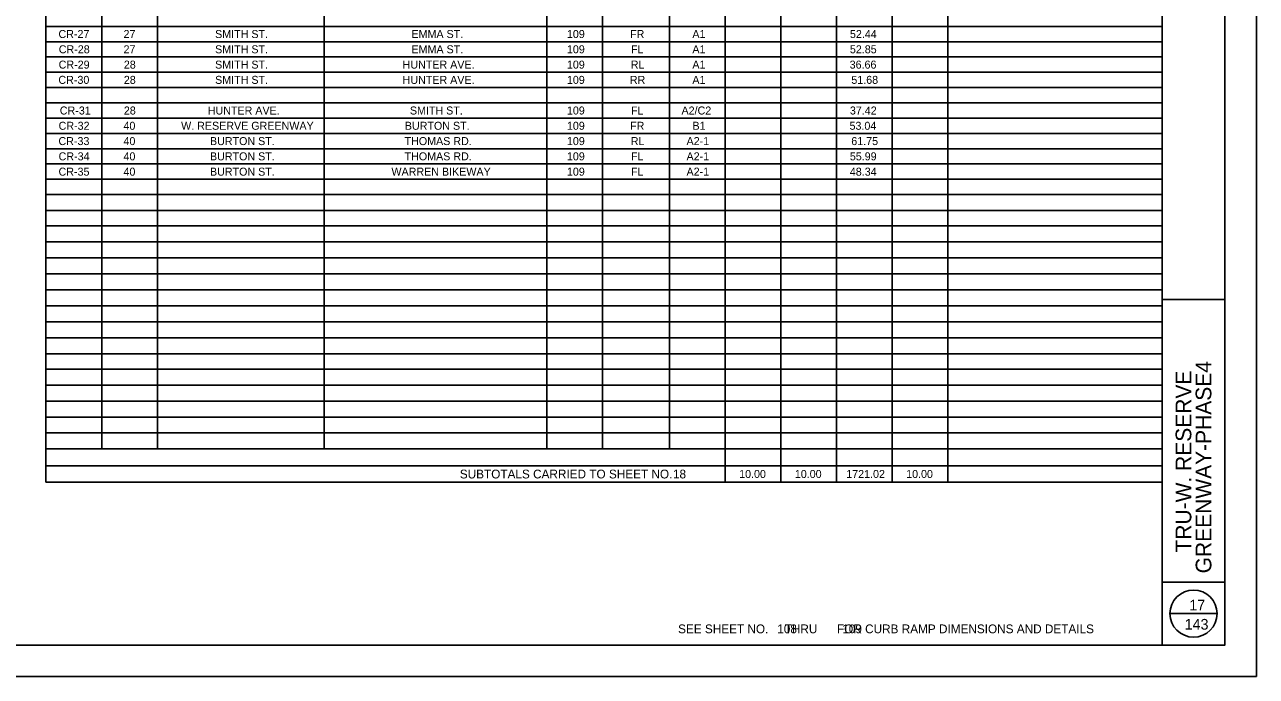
# Model space of a CAD drawing. Extents: x -16 to 102, y -13 to 9.
# Drawn here: x -1.97 to 17.63, y -12.91 to -2.53 of the extents above; entities that cross this region are included whole.
import ezdxf

# ---------------------------------------------------------------- set-up
doc = ezdxf.new("R2010")
doc.units = 0
for name, color, linetype in [('PV_P_EOP', 7, 'Continuous'), ('SH_Border', 7, 'Continuous'), ('SH_Cut_Line', 7, 'Continuous'), ('SH_Data', 7, 'Continuous'), ('TX_P_1', 7, 'Continuous')]:
    doc.layers.add(name, color=color, linetype=linetype)

msp = doc.modelspace()

# ---------------------------------------------------------------- linework, layer by layer
at = {"layer": 'SH_Border'}
for p, q in [((16.129, -12.407), (16.129, 8.593)), ((16.129, -6.907), (17.129, -6.907)), ((16.129, -11.407), (17.129, -11.407))]:
    msp.add_line(p, q, dxfattribs=at)
msp.add_lwpolyline([(-14.371, 8.593), (17.129, 8.593), (17.129, -12.407), (-14.371, -12.407)], close=True, dxfattribs=at)
at = {"layer": 'SH_Cut_Line'}
msp.add_lwpolyline([(-16.371, -12.907), (17.629, -12.907), (17.629, 9.093), (-16.371, 9.093)], close=True, dxfattribs=at)
at = {"layer": 'SH_Data'}
msp.add_line((16.254, -11.907), (17.004, -11.907), dxfattribs=at)
msp.add_circle((16.629, -11.907), 0.375, dxfattribs=at)
at = {"layer": 'TX_P_1'}
for p, q in [((-1.628, -2.067), (-1.628, -2.798)), ((-0.742, -2.067), (-0.742, -2.798)), ((0.144, -2.067), (0.144, -2.798)), ((2.8, -2.067), (2.8, -2.798)), ((6.343, -2.067), (6.343, -2.798)), ((7.228, -2.067), (7.228, -2.798)), ((8.291, -2.067), (8.291, -2.798)), ((9.177, -2.067), (9.177, -2.798)), ((10.062, -2.067), (10.062, -2.798)), ((10.948, -2.067), (10.948, -2.798)), ((11.834, -2.067), (11.834, -2.798)), ((12.719, -2.067), (12.719, -2.798)), ((16.129, -2.067), (16.129, -2.798)), ((-1.628, -2.554), (16.129, -2.554)), ((-1.628, -2.798), (16.129, -2.798)), ((-1.628, -2.798), (-1.628, -3.285)), ((-0.742, -2.798), (-0.742, -3.285)), ((0.144, -2.798), (0.144, -3.285)), ((2.8, -2.798), (2.8, -3.285)), ((6.343, -2.798), (6.343, -3.285)), ((7.228, -2.798), (7.228, -3.285)), ((8.291, -2.798), (8.291, -3.285)), ((9.177, -2.798), (9.177, -3.285)), ((10.062, -2.798), (10.062, -3.285)), ((10.948, -2.798), (10.948, -3.285)), ((11.834, -2.798), (11.834, -3.285)), ((12.719, -2.798), (12.719, -3.285)), ((16.129, -2.798), (16.129, -3.285)), ((-1.628, -3.042), (16.129, -3.042)), ((-1.628, -3.285), (16.129, -3.285)), ((-1.628, -3.285), (-1.628, -4.016)), ((-0.742, -3.285), (-0.742, -4.016)), ((0.144, -3.285), (0.144, -4.016)), ((2.8, -3.285), (2.8, -4.016)), ((6.343, -3.285), (6.343, -4.016)), ((7.228, -3.285), (7.228, -4.016)), ((8.291, -3.285), (8.291, -4.016)), ((9.177, -3.285), (9.177, -4.016)), ((10.062, -3.285), (10.062, -4.016)), ((10.948, -3.285), (10.948, -4.016)), ((11.834, -3.285), (11.834, -4.016)), ((12.719, -3.285), (12.719, -4.016)), ((16.129, -3.285), (16.129, -4.016)), ((-1.628, -3.529), (16.129, -3.529)), ((-1.628, -3.772), (16.129, -3.772)), ((-1.628, -4.016), (16.129, -4.016)), ((-1.628, -4.016), (-1.628, -4.503)), ((-0.742, -4.016), (-0.742, -4.503)), ((0.144, -4.016), (0.144, -4.503)), ((2.8, -4.016), (2.8, -4.503)), ((6.343, -4.016), (6.343, -4.503)), ((7.228, -4.016), (7.228, -4.503)), ((8.291, -4.016), (8.291, -4.503)), ((9.177, -4.016), (9.177, -4.503)), ((10.062, -4.016), (10.062, -4.503)), ((10.948, -4.016), (10.948, -4.503)), ((11.834, -4.016), (11.834, -4.503)), ((12.719, -4.016), (12.719, -4.503)), ((16.129, -4.016), (16.129, -4.503)), ((-1.628, -4.259), (16.129, -4.259)), ((-1.628, -4.503), (16.129, -4.503)), ((-1.628, -4.503), (-1.628, -5.233)), ((-0.742, -4.503), (-0.742, -5.233)), ((0.144, -4.503), (0.144, -5.233)), ((2.8, -4.503), (2.8, -5.233)), ((6.343, -4.503), (6.343, -5.233)), ((7.228, -4.503), (7.228, -5.233)), ((8.291, -4.503), (8.291, -5.233)), ((9.177, -4.503), (9.177, -5.233)), ((10.062, -4.503), (10.062, -5.233)), ((10.948, -4.503), (10.948, -5.233)), ((11.834, -4.503), (11.834, -5.233)), ((12.719, -4.503), (12.719, -5.233)), ((16.129, -4.503), (16.129, -5.233)), ((-1.628, -4.746), (16.129, -4.746)), ((-1.628, -4.99), (16.129, -4.99)), ((-1.628, -5.233), (16.129, -5.233)), ((-1.628, -5.233), (-1.628, -5.488)), ((-0.742, -5.233), (-0.742, -5.488)), ((0.144, -5.233), (0.144, -5.488)), ((2.8, -5.233), (2.8, -5.488)), ((6.343, -5.233), (6.343, -5.488)), ((7.228, -5.233), (7.228, -5.488)), ((8.291, -5.233), (8.291, -5.488)), ((9.177, -5.233), (9.177, -5.488)), ((10.062, -5.233), (10.062, -5.488)), ((10.948, -5.233), (10.948, -5.488)), ((11.834, -5.233), (11.834, -5.488)), ((12.719, -5.233), (12.719, -5.488)), ((16.129, -5.233), (16.129, -5.488)), ((-1.628, -5.488), (16.129, -5.488)), ((-1.628, -5.488), (-1.628, -5.732)), ((-0.742, -5.488), (-0.742, -5.732)), ((0.144, -5.488), (0.144, -5.732)), ((2.8, -5.488), (2.8, -5.732)), ((6.343, -5.488), (6.343, -5.732)), ((7.228, -5.488), (7.228, -5.732)), ((8.291, -5.488), (8.291, -5.732)), ((9.177, -5.488), (9.177, -5.732)), ((10.062, -5.488), (10.062, -5.732)), ((10.948, -5.488), (10.948, -5.732)), ((11.834, -5.488), (11.834, -5.732)), ((12.719, -5.488), (12.719, -5.732)), ((16.129, -5.488), (16.129, -5.732)), ((-1.628, -5.732), (16.129, -5.732)), ((-1.628, -5.732), (-1.628, -5.986)), ((-0.742, -5.732), (-0.742, -5.986)), ((0.144, -5.732), (0.144, -5.986)), ((2.8, -5.732), (2.8, -5.986)), ((6.343, -5.732), (6.343, -5.986)), ((7.228, -5.732), (7.228, -5.986)), ((8.291, -5.732), (8.291, -5.986)), ((9.177, -5.732), (9.177, -5.986)), ((10.062, -5.732), (10.062, -5.986)), ((10.948, -5.732), (10.948, -5.986)), ((11.834, -5.732), (11.834, -5.986)), ((12.719, -5.732), (12.719, -5.986)), ((16.129, -5.732), (16.129, -5.986)), ((-1.628, -5.986), (16.129, -5.986)), ((-1.628, -5.986), (-1.628, -6.75)), ((-0.742, -5.986), (-0.742, -6.75)), ((0.144, -5.986), (0.144, -6.75)), ((2.8, -5.986), (2.8, -6.75)), ((6.343, -5.986), (6.343, -6.75)), ((7.228, -5.986), (7.228, -6.75)), ((8.291, -5.986), (8.291, -6.75)), ((9.177, -5.986), (9.177, -6.75)), ((10.062, -5.986), (10.062, -6.75)), ((10.948, -5.986), (10.948, -6.75)), ((11.834, -5.986), (11.834, -6.75)), ((12.719, -5.986), (12.719, -6.75)), ((16.129, -5.986), (16.129, -6.75)), ((-1.628, -6.241), (16.129, -6.241)), ((-1.628, -6.495), (16.129, -6.495)), ((-1.628, -6.75), (16.129, -6.75)), ((-1.628, -6.75), (-1.628, -7.259)), ((-0.742, -6.75), (-0.742, -7.259)), ((0.144, -6.75), (0.144, -7.259)), ((2.8, -6.75), (2.8, -7.259)), ((6.343, -6.75), (6.343, -7.259)), ((7.228, -6.75), (7.228, -7.259)), ((8.291, -6.75), (8.291, -7.259)), ((9.177, -6.75), (9.177, -7.259)), ((10.062, -6.75), (10.062, -7.259)), ((10.948, -6.75), (10.948, -7.259)), ((11.834, -6.75), (11.834, -7.259)), ((12.719, -6.75), (12.719, -7.259)), ((16.129, -6.75), (16.129, -7.259)), ((-1.628, -7.005), (16.129, -7.005)), ((-1.628, -7.259), (16.129, -7.259)), ((-1.628, -7.259), (-1.628, -8.521)), ((-0.742, -7.259), (-0.742, -8.521)), ((0.144, -7.259), (0.144, -8.521)), ((2.8, -7.259), (2.8, -8.521)), ((6.343, -7.259), (6.343, -8.521)), ((7.228, -7.259), (7.228, -8.521)), ((8.291, -7.259), (8.291, -8.521)), ((9.177, -7.259), (9.177, -8.521)), ((10.062, -7.259), (10.062, -8.521)), ((10.948, -7.259), (10.948, -8.521)), ((11.834, -7.259), (11.834, -8.521)), ((12.719, -7.259), (12.719, -8.521)), ((16.129, -7.259), (16.129, -8.521)), ((-1.628, -7.514), (16.129, -7.514)), ((-1.628, -7.768), (16.129, -7.768)), ((-1.628, -8.012), (16.129, -8.012)), ((-1.628, -8.267), (16.129, -8.267)), ((-1.628, -8.521), (16.129, -8.521)), ((-1.628, -8.521), (-1.628, -9.03)), ((-0.742, -8.521), (-0.742, -9.03)), ((0.144, -8.521), (0.144, -9.03)), ((2.8, -8.521), (2.8, -9.03)), ((6.343, -8.521), (6.343, -9.03)), ((7.228, -8.521), (7.228, -9.03)), ((8.291, -8.521), (8.291, -9.03)), ((9.177, -8.521), (9.177, -9.03)), ((10.062, -8.521), (10.062, -9.03)), ((10.948, -8.521), (10.948, -9.03)), ((11.834, -8.521), (11.834, -9.03)), ((12.719, -8.521), (12.719, -9.03)), ((16.129, -8.521), (16.129, -9.03)), ((-1.628, -8.776), (16.129, -8.776)), ((-1.628, -9.03), (16.129, -9.03)), ((-1.628, -9.03), (-1.628, -9.816)), ((-0.742, -9.03), (-0.742, -9.285)), ((0.144, -9.03), (0.144, -9.285)), ((2.8, -9.03), (2.8, -9.285)), ((6.343, -9.03), (6.343, -9.285)), ((7.228, -9.03), (7.228, -9.285)), ((8.291, -9.03), (8.291, -9.285)), ((9.177, -9.03), (9.177, -9.816)), ((10.062, -9.03), (10.062, -9.816)), ((10.948, -9.03), (10.948, -9.816)), ((11.834, -9.03), (11.834, -9.816)), ((12.719, -9.03), (12.719, -9.816)), ((16.129, -9.03), (16.129, -9.816)), ((-1.628, -9.285), (16.129, -9.285)), ((-1.628, -9.551), (16.129, -9.551)), ((-1.628, -9.816), (16.129, -9.816))]:
    msp.add_line(p, q, dxfattribs=at)

# ---------------------------------------------------------------- texts
at = {"layer": 'PV_P_EOP'}
for s, height, p in [('SUBTOTALS CARRIED TO SHEET NO.', 0.14004, (4.956, -9.754)), ('18', 0.14, (8.347, -9.754))]:
    msp.add_text(s, height=height, dxfattribs=at).set_placement(p)
at = {"layer": 'SH_Data'}
for s, p in [('GREENWAY-PHASE4', (16.913, -11.266)), ('TRU-W. RESERVE', (16.594, -10.934))]:
    msp.add_text(s, height=0.25, rotation=90, dxfattribs=at).set_placement(p)
for s, p in [('17', (16.561, -11.857)), ('143', (16.488, -12.162))]:
    msp.add_text(s, height=0.17, dxfattribs=at).set_placement(p)
at = {"layer": 'TX_P_1'}
for s, height, p in [('CR-27', 0.1273, (-1.429, -2.74)), ('27', 0.1273, (-0.394, -2.74)), ('SMITH ST.', 0.1273, (1.063, -2.74)), ('EMMA ST.', 0.1273, (4.187, -2.74)), ('109', 0.1273, (6.66, -2.74)), ('FR', 0.1273, (7.665, -2.74)), ('A1', 0.1273, (8.656, -2.74)), ('52.44', 0.1273, (11.163, -2.74)), ('CR-28', 0.1273, (-1.424, -2.983)), ('27', 0.1273, (-0.394, -2.983)), ('SMITH ST.', 0.1273, (1.063, -2.983)), ('EMMA ST.', 0.1273, (4.187, -2.983)), ('109', 0.1273, (6.66, -2.983)), ('FL', 0.1273, (7.68, -2.983)), ('A1', 0.1273, (8.656, -2.983)), ('52.85', 0.1273, (11.162, -2.983)), ('CR-29', 0.1273, (-1.426, -3.227)), ('28', 0.1273, (-0.389, -3.227)), ('SMITH ST.', 0.1273, (1.063, -3.227)), ('HUNTER AVE.', 0.12731, (4.046, -3.227)), ('109', 0.1273, (6.66, -3.227)), ('RL', 0.1273, (7.676, -3.227)), ('A1', 0.1273, (8.656, -3.227)), ('36.66', 0.1273, (11.158, -3.227)), ('CR-30', 0.1273, (-1.43, -3.47)), ('28', 0.1273, (-0.389, -3.47)), ('SMITH ST.', 0.1273, (1.063, -3.47)), ('HUNTER AVE.', 0.12731, (4.046, -3.47)), ('109', 0.1273, (6.66, -3.47)), ('RR', 0.1273, (7.661, -3.47)), ('A1', 0.1273, (8.656, -3.47)), ('51.68', 0.1273, (11.185, -3.47)), ('CR-31', 0.1273, (-1.408, -3.958)), ('28', 0.1273, (-0.389, -3.958)), ('HUNTER AVE.', 0.12731, (0.946, -3.958)), ('SMITH ST.', 0.1273, (4.162, -3.958)), ('109', 0.1273, (6.66, -3.958)), ('FL', 0.1273, (7.68, -3.958)), ('A2/C2', 0.1273, (8.483, -3.958)), ('37.42', 0.1273, (11.162, -3.958)), ('CR-32', 0.1273, (-1.427, -4.201)), ('40', 0.1273, (-0.395, -4.201)), ('W. RESERVE GREENWAY', 0.12731, (0.522, -4.201)), ('BURTON ST.', 0.1273, (4.081, -4.201)), ('109', 0.1273, (6.66, -4.201)), ('FR', 0.1273, (7.665, -4.201)), ('B1', 0.1273, (8.657, -4.201)), ('53.04', 0.1273, (11.156, -4.201)), ('CR-33', 0.1273, (-1.429, -4.445)), ('40', 0.1273, (-0.395, -4.445)), ('BURTON ST.', 0.1273, (0.981, -4.445)), ('THOMAS RD.', 0.1273, (4.077, -4.445)), ('109', 0.1273, (6.66, -4.445)), ('RL', 0.1273, (7.676, -4.445)), ('A2-1', 0.1273, (8.563, -4.445)), ('61.75', 0.1273, (11.184, -4.445)), ('CR-34', 0.1273, (-1.427, -4.688)), ('40', 0.1273, (-0.395, -4.688)), ('BURTON ST.', 0.1273, (0.981, -4.688)), ('THOMAS RD.', 0.1273, (4.077, -4.688)), ('109', 0.1273, (6.66, -4.688)), ('FL', 0.1273, (7.68, -4.688)), ('A2-1', 0.1273, (8.563, -4.688)), ('55.99', 0.1273, (11.161, -4.688)), ('CR-35', 0.1273, (-1.428, -4.932)), ('40', 0.1273, (-0.395, -4.932)), ('BURTON ST.', 0.1273, (0.981, -4.932)), ('WARREN BIKEWAY', 0.12731, (3.868, -4.932)), ('109', 0.1273, (6.66, -4.932)), ('FL', 0.1273, (7.68, -4.932)), ('A2-1', 0.1273, (8.563, -4.932)), ('48.34', 0.1273, (11.161, -4.932)), ('10.00', 0.1273, (9.4, -9.747)), ('10.00', 0.1273, (10.286, -9.747)), ('1721.02', 0.1273, (11.104, -9.747)), ('10.00', 0.1273, (12.057, -9.747)), ('SEE SHEET NO.     THRU      FOR CURB RAMP DIMENSIONS AND DETAILS', 0.14, (8.429, -12.22)), ('108', 0.14, (10.006, -12.22)), ('109', 0.14, (11.041, -12.22))]:
    msp.add_text(s, height=height, dxfattribs=at).set_placement(p)

doc.saveas('drawing.dxf')
